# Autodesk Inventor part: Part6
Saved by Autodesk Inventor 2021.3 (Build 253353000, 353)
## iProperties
Created: 2022-03
Part Number: Part6
Material: Generic
Document SubType Name: Modeling
Designer: Administrator
Density: 1 g/cm^3
Appearance: Default
Author: Administrator
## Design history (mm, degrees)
feature "Body1"
body "Solid1"
